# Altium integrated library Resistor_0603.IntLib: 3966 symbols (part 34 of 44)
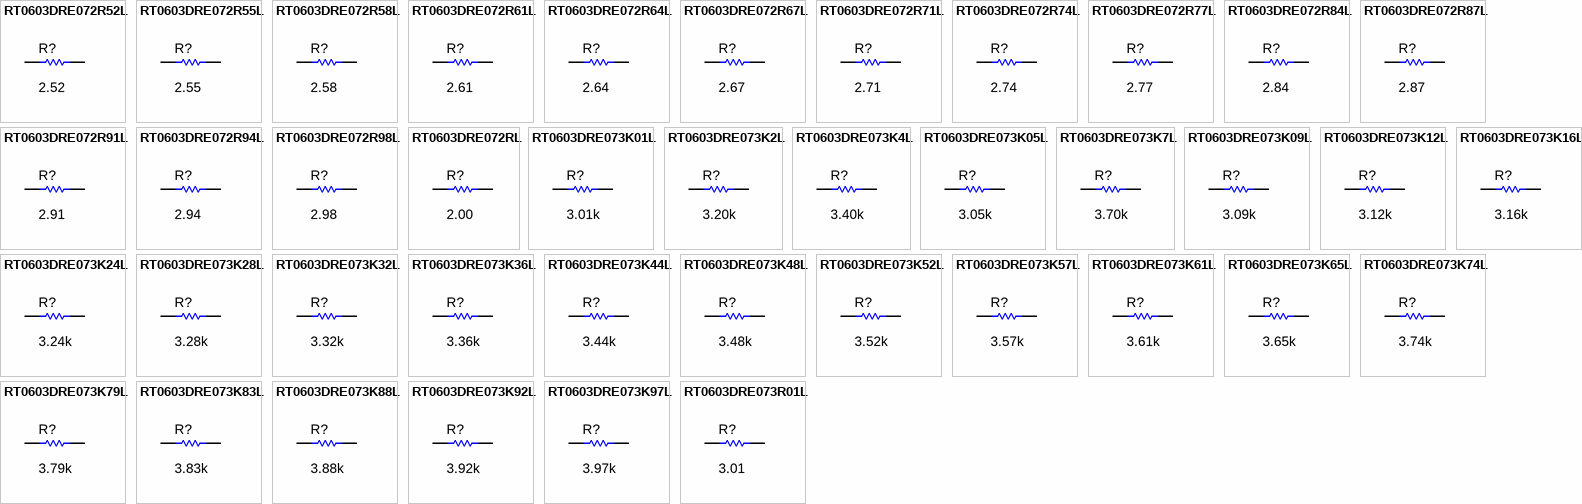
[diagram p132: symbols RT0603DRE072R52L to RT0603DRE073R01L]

## RT0603DRE073K01L
designator R?  ValueDisplayed: 3.01k  (hidden comment: RT0603DRE073K01L)
RES, 3.01 k, 0.5%, 0.1 W, 0603; Manufacturer: Yageo America; CompType: Resistor; Value: 3.01k; Res_ohm: 3010; Value_Code: 3k01; Tolerance_%: 0.5; Power_W: 0.1; Value2: 0.1W; VDC_V: 75; TempCo: 50 ppm/C; SizeArea_mm2: 1.28; SizeX_mm: 1.6; SizeY_mm: 0.8; SizeZ_mm: 1; EIA_Code: E192; U/M: EA; AEC Category: Q200
signal-integrity model Resistor
simulation model Resistor
footprint 0603
footprint 0603M
footprint 0603L
footprint 0603_HV
footprint 0603S
pins: 1, 2

## RT0603DRE073K2L
designator R?  ValueDisplayed: 3.20k  (hidden comment: RT0603DRE073K2L)
RES, 3.20 k, 0.5%, 0.1 W, 0603; Manufacturer: Yageo America; CompType: Resistor; Value: 3.20k; Res_ohm: 3200; Value_Code: 3k20; Tolerance_%: 0.5; Power_W: 0.1; Value2: 0.1W; VDC_V: 75; TempCo: 50 ppm/C; SizeArea_mm2: 1.28; SizeX_mm: 1.6; SizeY_mm: 0.8; SizeZ_mm: 1; EIA_Code: E192; U/M: EA; AEC Category: Q200
signal-integrity model Resistor
simulation model Resistor
footprint 0603
footprint 0603M
footprint 0603L
footprint 0603_HV
footprint 0603S
pins: 1, 2

## RT0603DRE073K4L
designator R?  ValueDisplayed: 3.40k  (hidden comment: RT0603DRE073K4L)
RES, 3.40 k, 0.5%, 0.1 W, 0603; Manufacturer: Yageo America; CompType: Resistor; Value: 3.40k; Res_ohm: 3400; Value_Code: 3k40; Tolerance_%: 0.5; Power_W: 0.1; Value2: 0.1W; VDC_V: 75; TempCo: 50 ppm/C; SizeArea_mm2: 1.28; SizeX_mm: 1.6; SizeY_mm: 0.8; SizeZ_mm: 1; EIA_Code: E192; U/M: EA; AEC Category: Q200
signal-integrity model Resistor
simulation model Resistor
footprint 0603
footprint 0603M
footprint 0603L
footprint 0603_HV
footprint 0603S
pins: 1, 2

## RT0603DRE073K05L
designator R?  ValueDisplayed: 3.05k  (hidden comment: RT0603DRE073K05L)
RES, 3.05 k, 0.5%, 0.1 W, 0603; Manufacturer: Yageo America; CompType: Resistor; Value: 3.05k; Res_ohm: 3050; Value_Code: 3k05; Tolerance_%: 0.5; Power_W: 0.1; Value2: 0.1W; VDC_V: 75; TempCo: 50 ppm/C; SizeArea_mm2: 1.28; SizeX_mm: 1.6; SizeY_mm: 0.8; SizeZ_mm: 1; EIA_Code: E192; U/M: EA; AEC Category: Q200
signal-integrity model Resistor
simulation model Resistor
footprint 0603
footprint 0603M
footprint 0603L
footprint 0603_HV
footprint 0603S
pins: 1, 2

## RT0603DRE073K7L
designator R?  ValueDisplayed: 3.70k  (hidden comment: RT0603DRE073K7L)
RES, 3.70 k, 0.5%, 0.1 W, 0603; Manufacturer: Yageo America; CompType: Resistor; Value: 3.70k; Res_ohm: 3700; Value_Code: 3k70; Tolerance_%: 0.5; Power_W: 0.1; Value2: 0.1W; VDC_V: 75; TempCo: 50 ppm/C; SizeArea_mm2: 1.28; SizeX_mm: 1.6; SizeY_mm: 0.8; SizeZ_mm: 1; EIA_Code: E192; U/M: EA; AEC Category: Q200
signal-integrity model Resistor
simulation model Resistor
footprint 0603
footprint 0603M
footprint 0603L
footprint 0603_HV
footprint 0603S
pins: 1, 2

## RT0603DRE073K09L
designator R?  ValueDisplayed: 3.09k  (hidden comment: RT0603DRE073K09L)
RES, 3.09 k, 0.5%, 0.1 W, 0603; Manufacturer: Yageo America; CompType: Resistor; Value: 3.09k; Res_ohm: 3090; Value_Code: 3k09; Tolerance_%: 0.5; Power_W: 0.1; Value2: 0.1W; VDC_V: 75; TempCo: 50 ppm/C; SizeArea_mm2: 1.28; SizeX_mm: 1.6; SizeY_mm: 0.8; SizeZ_mm: 1; EIA_Code: E192; U/M: EA; AEC Category: Q200
signal-integrity model Resistor
simulation model Resistor
footprint 0603
footprint 0603M
footprint 0603L
footprint 0603_HV
footprint 0603S
pins: 1, 2

## RT0603DRE073K12L
designator R?  ValueDisplayed: 3.12k  (hidden comment: RT0603DRE073K12L)
RES, 3.12 k, 0.5%, 0.1 W, 0603; Manufacturer: Yageo America; CompType: Resistor; Value: 3.12k; Res_ohm: 3120; Value_Code: 3k12; Tolerance_%: 0.5; Power_W: 0.1; Value2: 0.1W; VDC_V: 75; TempCo: 50 ppm/C; SizeArea_mm2: 1.28; SizeX_mm: 1.6; SizeY_mm: 0.8; SizeZ_mm: 1; EIA_Code: E192; U/M: EA; AEC Category: Q200
signal-integrity model Resistor
simulation model Resistor
footprint 0603
footprint 0603M
footprint 0603L
footprint 0603_HV
footprint 0603S
pins: 1, 2

## RT0603DRE073K16L
designator R?  ValueDisplayed: 3.16k  (hidden comment: RT0603DRE073K16L)
RES, 3.16 k, 0.5%, 0.1 W, 0603; Manufacturer: Yageo America; CompType: Resistor; Value: 3.16k; Res_ohm: 3160; Value_Code: 3k16; Tolerance_%: 0.5; Power_W: 0.1; Value2: 0.1W; VDC_V: 75; TempCo: 50 ppm/C; SizeArea_mm2: 1.28; SizeX_mm: 1.6; SizeY_mm: 0.8; SizeZ_mm: 1; EIA_Code: E192; U/M: EA; AEC Category: Q200
signal-integrity model Resistor
simulation model Resistor
footprint 0603
footprint 0603M
footprint 0603L
footprint 0603_HV
footprint 0603S
pins: 1, 2

## RT0603DRE073K24L
designator R?  ValueDisplayed: 3.24k  (hidden comment: RT0603DRE073K24L)
RES, 3.24 k, 0.5%, 0.1 W, 0603; Manufacturer: Yageo America; CompType: Resistor; Value: 3.24k; Res_ohm: 3240; Value_Code: 3k24; Tolerance_%: 0.5; Power_W: 0.1; Value2: 0.1W; VDC_V: 75; TempCo: 50 ppm/C; SizeArea_mm2: 1.28; SizeX_mm: 1.6; SizeY_mm: 0.8; SizeZ_mm: 1; EIA_Code: E192; U/M: EA; AEC Category: Q200
signal-integrity model Resistor
simulation model Resistor
footprint 0603
footprint 0603M
footprint 0603L
footprint 0603_HV
footprint 0603S
pins: 1, 2

## RT0603DRE073K28L
designator R?  ValueDisplayed: 3.28k  (hidden comment: RT0603DRE073K28L)
RES, 3.28 k, 0.5%, 0.1 W, 0603; Manufacturer: Yageo America; CompType: Resistor; Value: 3.28k; Res_ohm: 3280; Value_Code: 3k28; Tolerance_%: 0.5; Power_W: 0.1; Value2: 0.1W; VDC_V: 75; TempCo: 50 ppm/C; SizeArea_mm2: 1.28; SizeX_mm: 1.6; SizeY_mm: 0.8; SizeZ_mm: 1; EIA_Code: E192; U/M: EA; AEC Category: Q200
signal-integrity model Resistor
simulation model Resistor
footprint 0603
footprint 0603M
footprint 0603L
footprint 0603_HV
footprint 0603S
pins: 1, 2

## RT0603DRE073K32L
designator R?  ValueDisplayed: 3.32k  (hidden comment: RT0603DRE073K32L)
RES, 3.32 k, 0.5%, 0.1 W, 0603; Manufacturer: Yageo America; CompType: Resistor; Value: 3.32k; Res_ohm: 3320; Value_Code: 3k32; Tolerance_%: 0.5; Power_W: 0.1; Value2: 0.1W; VDC_V: 75; TempCo: 50 ppm/C; SizeArea_mm2: 1.28; SizeX_mm: 1.6; SizeY_mm: 0.8; SizeZ_mm: 1; EIA_Code: E192; U/M: EA; AEC Category: Q200
signal-integrity model Resistor
simulation model Resistor
footprint 0603
footprint 0603M
footprint 0603L
footprint 0603_HV
footprint 0603S
pins: 1, 2

## RT0603DRE073K36L
designator R?  ValueDisplayed: 3.36k  (hidden comment: RT0603DRE073K36L)
RES, 3.36 k, 0.5%, 0.1 W, 0603; Manufacturer: Yageo America; CompType: Resistor; Value: 3.36k; Res_ohm: 3360; Value_Code: 3k36; Tolerance_%: 0.5; Power_W: 0.1; Value2: 0.1W; VDC_V: 75; TempCo: 50 ppm/C; SizeArea_mm2: 1.28; SizeX_mm: 1.6; SizeY_mm: 0.8; SizeZ_mm: 1; EIA_Code: E192; U/M: EA; AEC Category: Q200
signal-integrity model Resistor
simulation model Resistor
footprint 0603
footprint 0603M
footprint 0603L
footprint 0603_HV
footprint 0603S
pins: 1, 2

## RT0603DRE073K44L
designator R?  ValueDisplayed: 3.44k  (hidden comment: RT0603DRE073K44L)
RES, 3.44 k, 0.5%, 0.1 W, 0603; Manufacturer: Yageo America; CompType: Resistor; Value: 3.44k; Res_ohm: 3440; Value_Code: 3k44; Tolerance_%: 0.5; Power_W: 0.1; Value2: 0.1W; VDC_V: 75; TempCo: 50 ppm/C; SizeArea_mm2: 1.28; SizeX_mm: 1.6; SizeY_mm: 0.8; SizeZ_mm: 1; EIA_Code: E192; U/M: EA; AEC Category: Q200
signal-integrity model Resistor
simulation model Resistor
footprint 0603
footprint 0603M
footprint 0603L
footprint 0603_HV
footprint 0603S
pins: 1, 2

## RT0603DRE073K48L
designator R?  ValueDisplayed: 3.48k  (hidden comment: RT0603DRE073K48L)
RES, 3.48 k, 0.5%, 0.1 W, 0603; Manufacturer: Yageo America; CompType: Resistor; Value: 3.48k; Res_ohm: 3480; Value_Code: 3k48; Tolerance_%: 0.5; Power_W: 0.1; Value2: 0.1W; VDC_V: 75; TempCo: 50 ppm/C; SizeArea_mm2: 1.28; SizeX_mm: 1.6; SizeY_mm: 0.8; SizeZ_mm: 1; EIA_Code: E192; U/M: EA; AEC Category: Q200
signal-integrity model Resistor
simulation model Resistor
footprint 0603
footprint 0603M
footprint 0603L
footprint 0603_HV
footprint 0603S
pins: 1, 2

## RT0603DRE073K52L
designator R?  ValueDisplayed: 3.52k  (hidden comment: RT0603DRE073K52L)
RES, 3.52 k, 0.5%, 0.1 W, 0603; Manufacturer: Yageo America; CompType: Resistor; Value: 3.52k; Res_ohm: 3520; Value_Code: 3k52; Tolerance_%: 0.5; Power_W: 0.1; Value2: 0.1W; VDC_V: 75; TempCo: 50 ppm/C; SizeArea_mm2: 1.28; SizeX_mm: 1.6; SizeY_mm: 0.8; SizeZ_mm: 1; EIA_Code: E192; U/M: EA; AEC Category: Q200
signal-integrity model Resistor
simulation model Resistor
footprint 0603
footprint 0603M
footprint 0603L
footprint 0603_HV
footprint 0603S
pins: 1, 2

## RT0603DRE073K57L
designator R?  ValueDisplayed: 3.57k  (hidden comment: RT0603DRE073K57L)
RES, 3.57 k, 0.5%, 0.1 W, 0603; Manufacturer: Yageo America; CompType: Resistor; Value: 3.57k; Res_ohm: 3570; Value_Code: 3k57; Tolerance_%: 0.5; Power_W: 0.1; Value2: 0.1W; VDC_V: 75; TempCo: 50 ppm/C; SizeArea_mm2: 1.28; SizeX_mm: 1.6; SizeY_mm: 0.8; SizeZ_mm: 1; EIA_Code: E192; U/M: EA; AEC Category: Q200
signal-integrity model Resistor
simulation model Resistor
footprint 0603
footprint 0603M
footprint 0603L
footprint 0603_HV
footprint 0603S
pins: 1, 2

## RT0603DRE073K61L
designator R?  ValueDisplayed: 3.61k  (hidden comment: RT0603DRE073K61L)
RES, 3.61 k, 0.5%, 0.1 W, 0603; Manufacturer: Yageo America; CompType: Resistor; Value: 3.61k; Res_ohm: 3610; Value_Code: 3k61; Tolerance_%: 0.5; Power_W: 0.1; Value2: 0.1W; VDC_V: 75; TempCo: 50 ppm/C; SizeArea_mm2: 1.28; SizeX_mm: 1.6; SizeY_mm: 0.8; SizeZ_mm: 1; EIA_Code: E192; U/M: EA; AEC Category: Q200
signal-integrity model Resistor
simulation model Resistor
footprint 0603
footprint 0603M
footprint 0603L
footprint 0603_HV
footprint 0603S
pins: 1, 2

## RT0603DRE073K65L
designator R?  ValueDisplayed: 3.65k  (hidden comment: RT0603DRE073K65L)
RES, 3.65 k, 0.5%, 0.1 W, 0603; Manufacturer: Yageo America; CompType: Resistor; Value: 3.65k; Res_ohm: 3650; Value_Code: 3k65; Tolerance_%: 0.5; Power_W: 0.1; Value2: 0.1W; VDC_V: 75; TempCo: 50 ppm/C; SizeArea_mm2: 1.28; SizeX_mm: 1.6; SizeY_mm: 0.8; SizeZ_mm: 1; EIA_Code: E192; U/M: EA; AEC Category: Q200
signal-integrity model Resistor
simulation model Resistor
footprint 0603
footprint 0603M
footprint 0603L
footprint 0603_HV
footprint 0603S
pins: 1, 2

## RT0603DRE073K74L
designator R?  ValueDisplayed: 3.74k  (hidden comment: RT0603DRE073K74L)
RES, 3.74 k, 0.5%, 0.1 W, 0603; Manufacturer: Yageo America; CompType: Resistor; Value: 3.74k; Res_ohm: 3740; Value_Code: 3k74; Tolerance_%: 0.5; Power_W: 0.1; Value2: 0.1W; VDC_V: 75; TempCo: 50 ppm/C; SizeArea_mm2: 1.28; SizeX_mm: 1.6; SizeY_mm: 0.8; SizeZ_mm: 1; EIA_Code: E192; U/M: EA; AEC Category: Q200
signal-integrity model Resistor
simulation model Resistor
footprint 0603
footprint 0603M
footprint 0603L
footprint 0603_HV
footprint 0603S
pins: 1, 2

## RT0603DRE073K79L
designator R?  ValueDisplayed: 3.79k  (hidden comment: RT0603DRE073K79L)
RES, 3.79 k, 0.5%, 0.1 W, 0603; Manufacturer: Yageo America; CompType: Resistor; Value: 3.79k; Res_ohm: 3790; Value_Code: 3k79; Tolerance_%: 0.5; Power_W: 0.1; Value2: 0.1W; VDC_V: 75; TempCo: 50 ppm/C; SizeArea_mm2: 1.28; SizeX_mm: 1.6; SizeY_mm: 0.8; SizeZ_mm: 1; EIA_Code: E192; U/M: EA; AEC Category: Q200
signal-integrity model Resistor
simulation model Resistor
footprint 0603
footprint 0603M
footprint 0603L
footprint 0603_HV
footprint 0603S
pins: 1, 2

## RT0603DRE073K83L
designator R?  ValueDisplayed: 3.83k  (hidden comment: RT0603DRE073K83L)
RES, 3.83 k, 0.5%, 0.1 W, 0603; Manufacturer: Yageo America; CompType: Resistor; Value: 3.83k; Res_ohm: 3830; Value_Code: 3k83; Tolerance_%: 0.5; Power_W: 0.1; Value2: 0.1W; VDC_V: 75; TempCo: 50 ppm/C; SizeArea_mm2: 1.28; SizeX_mm: 1.6; SizeY_mm: 0.8; SizeZ_mm: 1; EIA_Code: E192; U/M: EA; AEC Category: Q200
signal-integrity model Resistor
simulation model Resistor
footprint 0603
footprint 0603M
footprint 0603L
footprint 0603_HV
footprint 0603S
pins: 1, 2

## RT0603DRE073K88L
designator R?  ValueDisplayed: 3.88k  (hidden comment: RT0603DRE073K88L)
RES, 3.88 k, 0.5%, 0.1 W, 0603; Manufacturer: Yageo America; CompType: Resistor; Value: 3.88k; Res_ohm: 3880; Value_Code: 3k88; Tolerance_%: 0.5; Power_W: 0.1; Value2: 0.1W; VDC_V: 75; TempCo: 50 ppm/C; SizeArea_mm2: 1.28; SizeX_mm: 1.6; SizeY_mm: 0.8; SizeZ_mm: 1; EIA_Code: E192; U/M: EA; AEC Category: Q200
signal-integrity model Resistor
simulation model Resistor
footprint 0603
footprint 0603M
footprint 0603L
footprint 0603_HV
footprint 0603S
pins: 1, 2

## RT0603DRE073K92L
designator R?  ValueDisplayed: 3.92k  (hidden comment: RT0603DRE073K92L)
RES, 3.92 k, 0.5%, 0.1 W, 0603; Manufacturer: Yageo America; CompType: Resistor; Value: 3.92k; Res_ohm: 3920; Value_Code: 3k92; Tolerance_%: 0.5; Power_W: 0.1; Value2: 0.1W; VDC_V: 75; TempCo: 50 ppm/C; SizeArea_mm2: 1.28; SizeX_mm: 1.6; SizeY_mm: 0.8; SizeZ_mm: 1; EIA_Code: E192; U/M: EA; AEC Category: Q200
signal-integrity model Resistor
simulation model Resistor
footprint 0603
footprint 0603M
footprint 0603L
footprint 0603_HV
footprint 0603S
pins: 1, 2

## RT0603DRE073K97L
designator R?  ValueDisplayed: 3.97k  (hidden comment: RT0603DRE073K97L)
RES, 3.97 k, 0.5%, 0.1 W, 0603; Manufacturer: Yageo America; CompType: Resistor; Value: 3.97k; Res_ohm: 3970; Value_Code: 3k97; Tolerance_%: 0.5; Power_W: 0.1; Value2: 0.1W; VDC_V: 75; TempCo: 50 ppm/C; SizeArea_mm2: 1.28; SizeX_mm: 1.6; SizeY_mm: 0.8; SizeZ_mm: 1; EIA_Code: E192; U/M: EA; AEC Category: Q200
signal-integrity model Resistor
simulation model Resistor
footprint 0603
footprint 0603M
footprint 0603L
footprint 0603_HV
footprint 0603S
pins: 1, 2

## RT0603DRE073R01L
designator R?  ValueDisplayed: 3.01  (hidden comment: RT0603DRE073R01L)
RES, 3.01, 0.5%, 0.1 W, 0603; Manufacturer: Yageo America; CompType: Resistor; Value: 3.01; Value_Code: 3R01; Tolerance_%: 0.5; Power_W: 0.1; Value2: 0.1W; VDC_V: 75; TempCo: 50 ppm/C; SizeArea_mm2: 1.28; SizeX_mm: 1.6; SizeY_mm: 0.8; SizeZ_mm: 1; EIA_Code: E192; U/M: EA; AEC Category: Q200
signal-integrity model Resistor
simulation model Resistor
footprint 0603
footprint 0603M
footprint 0603L
footprint 0603_HV
footprint 0603S
pins: 1, 2

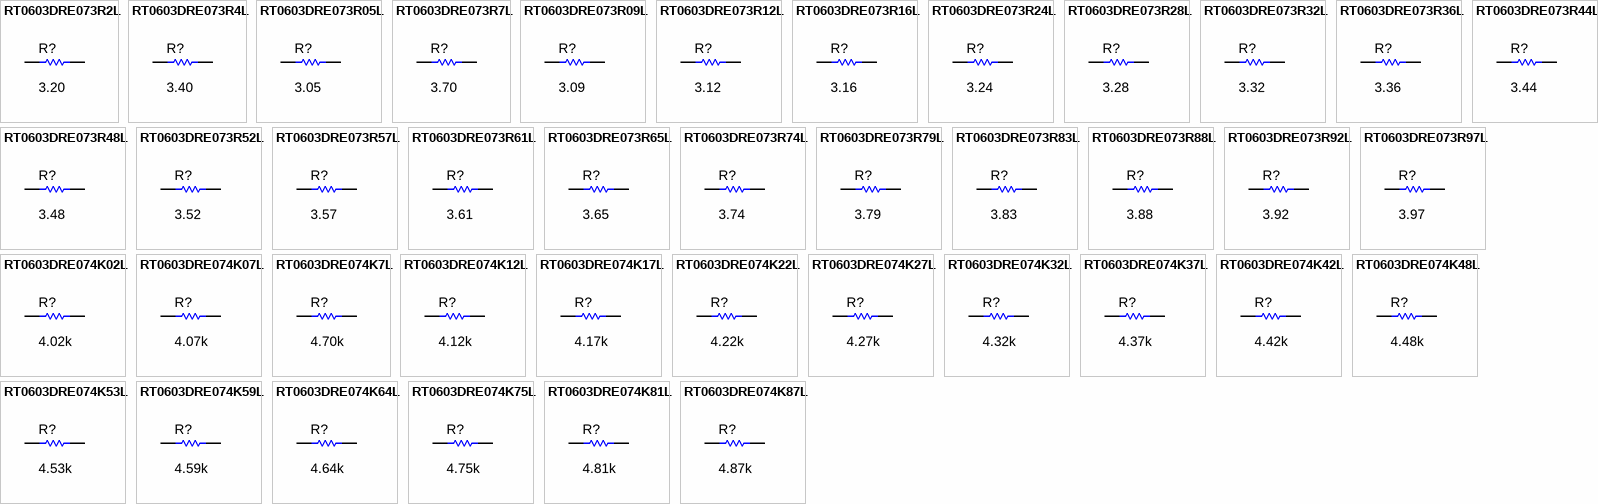
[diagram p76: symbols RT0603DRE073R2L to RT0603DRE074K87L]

## RT0603DRE073R2L
designator R?  ValueDisplayed: 3.20  (hidden comment: RT0603DRE073R2L)
RES, 3.20, 0.5%, 0.1 W, 0603; Manufacturer: Yageo America; CompType: Resistor; Value: 3.20; Res_ohm: 3.2; Value_Code: 3R20; Tolerance_%: 0.5; Power_W: 0.1; Value2: 0.1W; VDC_V: 75; TempCo: 50 ppm/C; SizeArea_mm2: 1.28; SizeX_mm: 1.6; SizeY_mm: 0.8; SizeZ_mm: 1; EIA_Code: E192; U/M: EA; AEC Category: Q200
signal-integrity model Resistor
simulation model Resistor
footprint 0603
footprint 0603M
footprint 0603L
footprint 0603_HV
footprint 0603S
pins: 1, 2

## RT0603DRE073R4L
designator R?  ValueDisplayed: 3.40  (hidden comment: RT0603DRE073R4L)
RES, 3.40, 0.5%, 0.1 W, 0603; Manufacturer: Yageo America; CompType: Resistor; Value: 3.40; Res_ohm: 3.4; Value_Code: 3R40; Tolerance_%: 0.5; Power_W: 0.1; Value2: 0.1W; VDC_V: 75; TempCo: 50 ppm/C; SizeArea_mm2: 1.28; SizeX_mm: 1.6; SizeY_mm: 0.8; SizeZ_mm: 1; EIA_Code: E192; U/M: EA; AEC Category: Q200
signal-integrity model Resistor
simulation model Resistor
footprint 0603
footprint 0603M
footprint 0603L
footprint 0603_HV
footprint 0603S
pins: 1, 2

## RT0603DRE073R05L
designator R?  ValueDisplayed: 3.05  (hidden comment: RT0603DRE073R05L)
RES, 3.05, 0.5%, 0.1 W, 0603; Manufacturer: Yageo America; CompType: Resistor; Value: 3.05; Value_Code: 3R05; Tolerance_%: 0.5; Power_W: 0.1; Value2: 0.1W; VDC_V: 75; TempCo: 50 ppm/C; SizeArea_mm2: 1.28; SizeX_mm: 1.6; SizeY_mm: 0.8; SizeZ_mm: 1; EIA_Code: E192; U/M: EA; AEC Category: Q200
signal-integrity model Resistor
simulation model Resistor
footprint 0603
footprint 0603M
footprint 0603L
footprint 0603_HV
footprint 0603S
pins: 1, 2

## RT0603DRE073R7L
designator R?  ValueDisplayed: 3.70  (hidden comment: RT0603DRE073R7L)
RES, 3.70, 0.5%, 0.1 W, 0603; Manufacturer: Yageo America; CompType: Resistor; Value: 3.70; Res_ohm: 3.7; Value_Code: 3R70; Tolerance_%: 0.5; Power_W: 0.1; Value2: 0.1W; VDC_V: 75; TempCo: 50 ppm/C; SizeArea_mm2: 1.28; SizeX_mm: 1.6; SizeY_mm: 0.8; SizeZ_mm: 1; EIA_Code: E192; U/M: EA; AEC Category: Q200
signal-integrity model Resistor
simulation model Resistor
footprint 0603
footprint 0603M
footprint 0603L
footprint 0603_HV
footprint 0603S
pins: 1, 2

## RT0603DRE073R09L
designator R?  ValueDisplayed: 3.09  (hidden comment: RT0603DRE073R09L)
RES, 3.09, 0.5%, 0.1 W, 0603; Manufacturer: Yageo America; CompType: Resistor; Value: 3.09; Value_Code: 3R09; Tolerance_%: 0.5; Power_W: 0.1; Value2: 0.1W; VDC_V: 75; TempCo: 50 ppm/C; SizeArea_mm2: 1.28; SizeX_mm: 1.6; SizeY_mm: 0.8; SizeZ_mm: 1; EIA_Code: E192; U/M: EA; AEC Category: Q200
signal-integrity model Resistor
simulation model Resistor
footprint 0603
footprint 0603M
footprint 0603L
footprint 0603_HV
footprint 0603S
pins: 1, 2

## RT0603DRE073R12L
designator R?  ValueDisplayed: 3.12  (hidden comment: RT0603DRE073R12L)
RES, 3.12, 0.5%, 0.1 W, 0603; Manufacturer: Yageo America; CompType: Resistor; Value: 3.12; Value_Code: 3R12; Tolerance_%: 0.5; Power_W: 0.1; Value2: 0.1W; VDC_V: 75; TempCo: 50 ppm/C; SizeArea_mm2: 1.28; SizeX_mm: 1.6; SizeY_mm: 0.8; SizeZ_mm: 1; EIA_Code: E192; U/M: EA; AEC Category: Q200
signal-integrity model Resistor
simulation model Resistor
footprint 0603
footprint 0603M
footprint 0603L
footprint 0603_HV
footprint 0603S
pins: 1, 2

## RT0603DRE073R16L
designator R?  ValueDisplayed: 3.16  (hidden comment: RT0603DRE073R16L)
RES, 3.16, 0.5%, 0.1 W, 0603; Manufacturer: Yageo America; CompType: Resistor; Value: 3.16; Value_Code: 3R16; Tolerance_%: 0.5; Power_W: 0.1; Value2: 0.1W; VDC_V: 75; TempCo: 50 ppm/C; SizeArea_mm2: 1.28; SizeX_mm: 1.6; SizeY_mm: 0.8; SizeZ_mm: 1; EIA_Code: E192; U/M: EA; AEC Category: Q200
signal-integrity model Resistor
simulation model Resistor
footprint 0603
footprint 0603M
footprint 0603L
footprint 0603_HV
footprint 0603S
pins: 1, 2

## RT0603DRE073R24L
designator R?  ValueDisplayed: 3.24  (hidden comment: RT0603DRE073R24L)
RES, 3.24, 0.5%, 0.1 W, 0603; Manufacturer: Yageo America; CompType: Resistor; Value: 3.24; Value_Code: 3R24; Tolerance_%: 0.5; Power_W: 0.1; Value2: 0.1W; VDC_V: 75; TempCo: 50 ppm/C; SizeArea_mm2: 1.28; SizeX_mm: 1.6; SizeY_mm: 0.8; SizeZ_mm: 1; EIA_Code: E192; U/M: EA; AEC Category: Q200
signal-integrity model Resistor
simulation model Resistor
footprint 0603
footprint 0603M
footprint 0603L
footprint 0603_HV
footprint 0603S
pins: 1, 2

## RT0603DRE073R28L
designator R?  ValueDisplayed: 3.28  (hidden comment: RT0603DRE073R28L)
RES, 3.28, 0.5%, 0.1 W, 0603; Manufacturer: Yageo America; CompType: Resistor; Value: 3.28; Value_Code: 3R28; Tolerance_%: 0.5; Power_W: 0.1; Value2: 0.1W; VDC_V: 75; TempCo: 50 ppm/C; SizeArea_mm2: 1.28; SizeX_mm: 1.6; SizeY_mm: 0.8; SizeZ_mm: 1; EIA_Code: E192; U/M: EA; AEC Category: Q200
signal-integrity model Resistor
simulation model Resistor
footprint 0603
footprint 0603M
footprint 0603L
footprint 0603_HV
footprint 0603S
pins: 1, 2

## RT0603DRE073R32L
designator R?  ValueDisplayed: 3.32  (hidden comment: RT0603DRE073R32L)
RES, 3.32, 0.5%, 0.1 W, 0603; Manufacturer: Yageo America; CompType: Resistor; Value: 3.32; Value_Code: 3R32; Tolerance_%: 0.5; Power_W: 0.1; Value2: 0.1W; VDC_V: 75; TempCo: 50 ppm/C; SizeArea_mm2: 1.28; SizeX_mm: 1.6; SizeY_mm: 0.8; SizeZ_mm: 1; EIA_Code: E192; U/M: EA; AEC Category: Q200
signal-integrity model Resistor
simulation model Resistor
footprint 0603
footprint 0603M
footprint 0603L
footprint 0603_HV
footprint 0603S
pins: 1, 2

## RT0603DRE073R36L
designator R?  ValueDisplayed: 3.36  (hidden comment: RT0603DRE073R36L)
RES, 3.36, 0.5%, 0.1 W, 0603; Manufacturer: Yageo America; CompType: Resistor; Value: 3.36; Value_Code: 3R36; Tolerance_%: 0.5; Power_W: 0.1; Value2: 0.1W; VDC_V: 75; TempCo: 50 ppm/C; SizeArea_mm2: 1.28; SizeX_mm: 1.6; SizeY_mm: 0.8; SizeZ_mm: 1; EIA_Code: E192; U/M: EA; AEC Category: Q200
signal-integrity model Resistor
simulation model Resistor
footprint 0603
footprint 0603M
footprint 0603L
footprint 0603_HV
footprint 0603S
pins: 1, 2

## RT0603DRE073R44L
designator R?  ValueDisplayed: 3.44  (hidden comment: RT0603DRE073R44L)
RES, 3.44, 0.5%, 0.1 W, 0603; Manufacturer: Yageo America; CompType: Resistor; Value: 3.44; Value_Code: 3R44; Tolerance_%: 0.5; Power_W: 0.1; Value2: 0.1W; VDC_V: 75; TempCo: 50 ppm/C; SizeArea_mm2: 1.28; SizeX_mm: 1.6; SizeY_mm: 0.8; SizeZ_mm: 1; EIA_Code: E192; U/M: EA; AEC Category: Q200
signal-integrity model Resistor
simulation model Resistor
footprint 0603
footprint 0603M
footprint 0603L
footprint 0603_HV
footprint 0603S
pins: 1, 2

## RT0603DRE073R48L
designator R?  ValueDisplayed: 3.48  (hidden comment: RT0603DRE073R48L)
RES, 3.48, 0.5%, 0.1 W, 0603; Manufacturer: Yageo America; CompType: Resistor; Value: 3.48; Value_Code: 3R48; Tolerance_%: 0.5; Power_W: 0.1; Value2: 0.1W; VDC_V: 75; TempCo: 50 ppm/C; SizeArea_mm2: 1.28; SizeX_mm: 1.6; SizeY_mm: 0.8; SizeZ_mm: 1; EIA_Code: E192; U/M: EA; AEC Category: Q200
signal-integrity model Resistor
simulation model Resistor
footprint 0603
footprint 0603M
footprint 0603L
footprint 0603_HV
footprint 0603S
pins: 1, 2

## RT0603DRE073R52L
designator R?  ValueDisplayed: 3.52  (hidden comment: RT0603DRE073R52L)
RES, 3.52, 0.5%, 0.1 W, 0603; Manufacturer: Yageo America; CompType: Resistor; Value: 3.52; Value_Code: 3R52; Tolerance_%: 0.5; Power_W: 0.1; Value2: 0.1W; VDC_V: 75; TempCo: 50 ppm/C; SizeArea_mm2: 1.28; SizeX_mm: 1.6; SizeY_mm: 0.8; SizeZ_mm: 1; EIA_Code: E192; U/M: EA; AEC Category: Q200
signal-integrity model Resistor
simulation model Resistor
footprint 0603
footprint 0603M
footprint 0603L
footprint 0603_HV
footprint 0603S
pins: 1, 2

## RT0603DRE073R57L
designator R?  ValueDisplayed: 3.57  (hidden comment: RT0603DRE073R57L)
RES, 3.57, 0.5%, 0.1 W, 0603; Manufacturer: Yageo America; CompType: Resistor; Value: 3.57; Value_Code: 3R57; Tolerance_%: 0.5; Power_W: 0.1; Value2: 0.1W; VDC_V: 75; TempCo: 50 ppm/C; SizeArea_mm2: 1.28; SizeX_mm: 1.6; SizeY_mm: 0.8; SizeZ_mm: 1; EIA_Code: E192; U/M: EA; AEC Category: Q200
signal-integrity model Resistor
simulation model Resistor
footprint 0603
footprint 0603M
footprint 0603L
footprint 0603_HV
footprint 0603S
pins: 1, 2

## RT0603DRE073R61L
designator R?  ValueDisplayed: 3.61  (hidden comment: RT0603DRE073R61L)
RES, 3.61, 0.5%, 0.1 W, 0603; Manufacturer: Yageo America; CompType: Resistor; Value: 3.61; Value_Code: 3R61; Tolerance_%: 0.5; Power_W: 0.1; Value2: 0.1W; VDC_V: 75; TempCo: 50 ppm/C; SizeArea_mm2: 1.28; SizeX_mm: 1.6; SizeY_mm: 0.8; SizeZ_mm: 1; EIA_Code: E192; U/M: EA; AEC Category: Q200
signal-integrity model Resistor
simulation model Resistor
footprint 0603
footprint 0603M
footprint 0603L
footprint 0603_HV
footprint 0603S
pins: 1, 2

## RT0603DRE073R65L
designator R?  ValueDisplayed: 3.65  (hidden comment: RT0603DRE073R65L)
RES, 3.65, 0.5%, 0.1 W, 0603; Manufacturer: Yageo America; CompType: Resistor; Value: 3.65; Value_Code: 3R65; Tolerance_%: 0.5; Power_W: 0.1; Value2: 0.1W; VDC_V: 75; TempCo: 50 ppm/C; SizeArea_mm2: 1.28; SizeX_mm: 1.6; SizeY_mm: 0.8; SizeZ_mm: 1; EIA_Code: E192; U/M: EA; AEC Category: Q200
signal-integrity model Resistor
simulation model Resistor
footprint 0603
footprint 0603M
footprint 0603L
footprint 0603_HV
footprint 0603S
pins: 1, 2

## RT0603DRE073R74L
designator R?  ValueDisplayed: 3.74  (hidden comment: RT0603DRE073R74L)
RES, 3.74, 0.5%, 0.1 W, 0603; Manufacturer: Yageo America; CompType: Resistor; Value: 3.74; Value_Code: 3R74; Tolerance_%: 0.5; Power_W: 0.1; Value2: 0.1W; VDC_V: 75; TempCo: 50 ppm/C; SizeArea_mm2: 1.28; SizeX_mm: 1.6; SizeY_mm: 0.8; SizeZ_mm: 1; EIA_Code: E192; U/M: EA; AEC Category: Q200
signal-integrity model Resistor
simulation model Resistor
footprint 0603
footprint 0603M
footprint 0603L
footprint 0603_HV
footprint 0603S
pins: 1, 2

## RT0603DRE073R79L
designator R?  ValueDisplayed: 3.79  (hidden comment: RT0603DRE073R79L)
RES, 3.79, 0.5%, 0.1 W, 0603; Manufacturer: Yageo America; CompType: Resistor; Value: 3.79; Value_Code: 3R79; Tolerance_%: 0.5; Power_W: 0.1; Value2: 0.1W; VDC_V: 75; TempCo: 50 ppm/C; SizeArea_mm2: 1.28; SizeX_mm: 1.6; SizeY_mm: 0.8; SizeZ_mm: 1; EIA_Code: E192; U/M: EA; AEC Category: Q200
signal-integrity model Resistor
simulation model Resistor
footprint 0603
footprint 0603M
footprint 0603L
footprint 0603_HV
footprint 0603S
pins: 1, 2

## RT0603DRE073R83L
designator R?  ValueDisplayed: 3.83  (hidden comment: RT0603DRE073R83L)
RES, 3.83, 0.5%, 0.1 W, 0603; Manufacturer: Yageo America; CompType: Resistor; Value: 3.83; Value_Code: 3R83; Tolerance_%: 0.5; Power_W: 0.1; Value2: 0.1W; VDC_V: 75; TempCo: 50 ppm/C; SizeArea_mm2: 1.28; SizeX_mm: 1.6; SizeY_mm: 0.8; SizeZ_mm: 1; EIA_Code: E192; U/M: EA; AEC Category: Q200
signal-integrity model Resistor
simulation model Resistor
footprint 0603
footprint 0603M
footprint 0603L
footprint 0603_HV
footprint 0603S
pins: 1, 2

## RT0603DRE073R88L
designator R?  ValueDisplayed: 3.88  (hidden comment: RT0603DRE073R88L)
RES, 3.88, 0.5%, 0.1 W, 0603; Manufacturer: Yageo America; CompType: Resistor; Value: 3.88; Value_Code: 3R88; Tolerance_%: 0.5; Power_W: 0.1; Value2: 0.1W; VDC_V: 75; TempCo: 50 ppm/C; SizeArea_mm2: 1.28; SizeX_mm: 1.6; SizeY_mm: 0.8; SizeZ_mm: 1; EIA_Code: E192; U/M: EA; AEC Category: Q200
signal-integrity model Resistor
simulation model Resistor
footprint 0603
footprint 0603M
footprint 0603L
footprint 0603_HV
footprint 0603S
pins: 1, 2

## RT0603DRE073R92L
designator R?  ValueDisplayed: 3.92  (hidden comment: RT0603DRE073R92L)
RES, 3.92, 0.5%, 0.1 W, 0603; Manufacturer: Yageo America; CompType: Resistor; Value: 3.92; Value_Code: 3R92; Tolerance_%: 0.5; Power_W: 0.1; Value2: 0.1W; VDC_V: 75; TempCo: 50 ppm/C; SizeArea_mm2: 1.28; SizeX_mm: 1.6; SizeY_mm: 0.8; SizeZ_mm: 1; EIA_Code: E192; U/M: EA; AEC Category: Q200
signal-integrity model Resistor
simulation model Resistor
footprint 0603
footprint 0603M
footprint 0603L
footprint 0603_HV
footprint 0603S
pins: 1, 2

## RT0603DRE073R97L
designator R?  ValueDisplayed: 3.97  (hidden comment: RT0603DRE073R97L)
RES, 3.97, 0.5%, 0.1 W, 0603; Manufacturer: Yageo America; CompType: Resistor; Value: 3.97; Value_Code: 3R97; Tolerance_%: 0.5; Power_W: 0.1; Value2: 0.1W; VDC_V: 75; TempCo: 50 ppm/C; SizeArea_mm2: 1.28; SizeX_mm: 1.6; SizeY_mm: 0.8; SizeZ_mm: 1; EIA_Code: E192; U/M: EA; AEC Category: Q200
signal-integrity model Resistor
simulation model Resistor
footprint 0603
footprint 0603M
footprint 0603L
footprint 0603_HV
footprint 0603S
pins: 1, 2

## RT0603DRE074K02L
designator R?  ValueDisplayed: 4.02k  (hidden comment: RT0603DRE074K02L)
RES, 4.02 k, 0.5%, 0.1 W, 0603; Manufacturer: Yageo America; CompType: Resistor; Value: 4.02k; Res_ohm: 4020; Value_Code: 4k02; Tolerance_%: 0.5; Power_W: 0.1; Value2: 0.1W; VDC_V: 75; TempCo: 50 ppm/C; SizeArea_mm2: 1.28; SizeX_mm: 1.6; SizeY_mm: 0.8; SizeZ_mm: 1; EIA_Code: E192; U/M: EA; AEC Category: Q200
signal-integrity model Resistor
simulation model Resistor
footprint 0603
footprint 0603M
footprint 0603L
footprint 0603_HV
footprint 0603S
pins: 1, 2

## RT0603DRE074K07L
designator R?  ValueDisplayed: 4.07k  (hidden comment: RT0603DRE074K07L)
RES, 4.07 k, 0.5%, 0.1 W, 0603; Manufacturer: Yageo America; CompType: Resistor; Value: 4.07k; Res_ohm: 4070; Value_Code: 4k07; Tolerance_%: 0.5; Power_W: 0.1; Value2: 0.1W; VDC_V: 75; TempCo: 50 ppm/C; SizeArea_mm2: 1.28; SizeX_mm: 1.6; SizeY_mm: 0.8; SizeZ_mm: 1; EIA_Code: E192; U/M: EA; AEC Category: Q200
signal-integrity model Resistor
simulation model Resistor
footprint 0603
footprint 0603M
footprint 0603L
footprint 0603_HV
footprint 0603S
pins: 1, 2

## RT0603DRE074K7L
designator R?  ValueDisplayed: 4.70k  (hidden comment: RT0603DRE074K7L)
RES, 4.70 k, 0.5%, 0.1 W, 0603; Manufacturer: Yageo America; CompType: Resistor; Value: 4.70k; Res_ohm: 4700; Value_Code: 4k70; Tolerance_%: 0.5; Power_W: 0.1; Value2: 0.1W; VDC_V: 75; TempCo: 50 ppm/C; SizeArea_mm2: 1.28; SizeX_mm: 1.6; SizeY_mm: 0.8; SizeZ_mm: 1; EIA_Code: E192; U/M: EA; AEC Category: Q200
signal-integrity model Resistor
simulation model Resistor
footprint 0603
footprint 0603M
footprint 0603L
footprint 0603_HV
footprint 0603S
pins: 1, 2

## RT0603DRE074K12L
designator R?  ValueDisplayed: 4.12k  (hidden comment: RT0603DRE074K12L)
RES, 4.12 k, 0.5%, 0.1 W, 0603; Manufacturer: Yageo America; CompType: Resistor; Value: 4.12k; Res_ohm: 4120; Value_Code: 4k12; Tolerance_%: 0.5; Power_W: 0.1; Value2: 0.1W; VDC_V: 75; TempCo: 50 ppm/C; SizeArea_mm2: 1.28; SizeX_mm: 1.6; SizeY_mm: 0.8; SizeZ_mm: 1; EIA_Code: E192; U/M: EA; AEC Category: Q200
signal-integrity model Resistor
simulation model Resistor
footprint 0603
footprint 0603M
footprint 0603L
footprint 0603_HV
footprint 0603S
pins: 1, 2

## RT0603DRE074K17L
designator R?  ValueDisplayed: 4.17k  (hidden comment: RT0603DRE074K17L)
RES, 4.17 k, 0.5%, 0.1 W, 0603; Manufacturer: Yageo America; CompType: Resistor; Value: 4.17k; Res_ohm: 4170; Value_Code: 4k17; Tolerance_%: 0.5; Power_W: 0.1; Value2: 0.1W; VDC_V: 75; TempCo: 50 ppm/C; SizeArea_mm2: 1.28; SizeX_mm: 1.6; SizeY_mm: 0.8; SizeZ_mm: 1; EIA_Code: E192; U/M: EA; AEC Category: Q200
signal-integrity model Resistor
simulation model Resistor
footprint 0603
footprint 0603M
footprint 0603L
footprint 0603_HV
footprint 0603S
pins: 1, 2

## RT0603DRE074K22L
designator R?  ValueDisplayed: 4.22k  (hidden comment: RT0603DRE074K22L)
RES, 4.22 k, 0.5%, 0.1 W, 0603; Manufacturer: Yageo America; CompType: Resistor; Value: 4.22k; Res_ohm: 4220; Value_Code: 4k22; Tolerance_%: 0.5; Power_W: 0.1; Value2: 0.1W; VDC_V: 75; TempCo: 50 ppm/C; SizeArea_mm2: 1.28; SizeX_mm: 1.6; SizeY_mm: 0.8; SizeZ_mm: 1; EIA_Code: E192; U/M: EA; AEC Category: Q200
signal-integrity model Resistor
simulation model Resistor
footprint 0603
footprint 0603M
footprint 0603L
footprint 0603_HV
footprint 0603S
pins: 1, 2

## RT0603DRE074K27L
designator R?  ValueDisplayed: 4.27k  (hidden comment: RT0603DRE074K27L)
RES, 4.27 k, 0.5%, 0.1 W, 0603; Manufacturer: Yageo America; CompType: Resistor; Value: 4.27k; Res_ohm: 4270; Value_Code: 4k27; Tolerance_%: 0.5; Power_W: 0.1; Value2: 0.1W; VDC_V: 75; TempCo: 50 ppm/C; SizeArea_mm2: 1.28; SizeX_mm: 1.6; SizeY_mm: 0.8; SizeZ_mm: 1; EIA_Code: E192; U/M: EA; AEC Category: Q200
signal-integrity model Resistor
simulation model Resistor
footprint 0603
footprint 0603M
footprint 0603L
footprint 0603_HV
footprint 0603S
pins: 1, 2

## RT0603DRE074K32L
designator R?  ValueDisplayed: 4.32k  (hidden comment: RT0603DRE074K32L)
RES, 4.32 k, 0.5%, 0.1 W, 0603; Manufacturer: Yageo America; CompType: Resistor; Value: 4.32k; Res_ohm: 4320; Value_Code: 4k32; Tolerance_%: 0.5; Power_W: 0.1; Value2: 0.1W; VDC_V: 75; TempCo: 50 ppm/C; SizeArea_mm2: 1.28; SizeX_mm: 1.6; SizeY_mm: 0.8; SizeZ_mm: 1; EIA_Code: E192; U/M: EA; AEC Category: Q200
signal-integrity model Resistor
simulation model Resistor
footprint 0603
footprint 0603M
footprint 0603L
footprint 0603_HV
footprint 0603S
pins: 1, 2

## RT0603DRE074K37L
designator R?  ValueDisplayed: 4.37k  (hidden comment: RT0603DRE074K37L)
RES, 4.37 k, 0.5%, 0.1 W, 0603; Manufacturer: Yageo America; CompType: Resistor; Value: 4.37k; Res_ohm: 4370; Value_Code: 4k37; Tolerance_%: 0.5; Power_W: 0.1; Value2: 0.1W; VDC_V: 75; TempCo: 50 ppm/C; SizeArea_mm2: 1.28; SizeX_mm: 1.6; SizeY_mm: 0.8; SizeZ_mm: 1; EIA_Code: E192; U/M: EA; AEC Category: Q200
signal-integrity model Resistor
simulation model Resistor
footprint 0603
footprint 0603M
footprint 0603L
footprint 0603_HV
footprint 0603S
pins: 1, 2

## RT0603DRE074K42L
designator R?  ValueDisplayed: 4.42k  (hidden comment: RT0603DRE074K42L)
RES, 4.42 k, 0.5%, 0.1 W, 0603; Manufacturer: Yageo America; CompType: Resistor; Value: 4.42k; Res_ohm: 4420; Value_Code: 4k42; Tolerance_%: 0.5; Power_W: 0.1; Value2: 0.1W; VDC_V: 75; TempCo: 50 ppm/C; SizeArea_mm2: 1.28; SizeX_mm: 1.6; SizeY_mm: 0.8; SizeZ_mm: 1; EIA_Code: E192; U/M: EA; AEC Category: Q200
signal-integrity model Resistor
simulation model Resistor
footprint 0603
footprint 0603M
footprint 0603L
footprint 0603_HV
footprint 0603S
pins: 1, 2

## RT0603DRE074K48L
designator R?  ValueDisplayed: 4.48k  (hidden comment: RT0603DRE074K48L)
RES, 4.48 k, 0.5%, 0.1 W, 0603; Manufacturer: Yageo America; CompType: Resistor; Value: 4.48k; Res_ohm: 4480; Value_Code: 4k48; Tolerance_%: 0.5; Power_W: 0.1; Value2: 0.1W; VDC_V: 75; TempCo: 50 ppm/C; SizeArea_mm2: 1.28; SizeX_mm: 1.6; SizeY_mm: 0.8; SizeZ_mm: 1; EIA_Code: E192; U/M: EA; AEC Category: Q200
signal-integrity model Resistor
simulation model Resistor
footprint 0603
footprint 0603M
footprint 0603L
footprint 0603_HV
footprint 0603S
pins: 1, 2

## RT0603DRE074K53L
designator R?  ValueDisplayed: 4.53k  (hidden comment: RT0603DRE074K53L)
RES, 4.53 k, 0.5%, 0.1 W, 0603; Manufacturer: Yageo America; CompType: Resistor; Value: 4.53k; Res_ohm: 4530; Value_Code: 4k53; Tolerance_%: 0.5; Power_W: 0.1; Value2: 0.1W; VDC_V: 75; TempCo: 50 ppm/C; SizeArea_mm2: 1.28; SizeX_mm: 1.6; SizeY_mm: 0.8; SizeZ_mm: 1; EIA_Code: E192; U/M: EA; AEC Category: Q200
signal-integrity model Resistor
simulation model Resistor
footprint 0603
footprint 0603M
footprint 0603L
footprint 0603_HV
footprint 0603S
pins: 1, 2

## RT0603DRE074K59L
designator R?  ValueDisplayed: 4.59k  (hidden comment: RT0603DRE074K59L)
RES, 4.59 k, 0.5%, 0.1 W, 0603; Manufacturer: Yageo America; CompType: Resistor; Value: 4.59k; Res_ohm: 4590; Value_Code: 4k59; Tolerance_%: 0.5; Power_W: 0.1; Value2: 0.1W; VDC_V: 75; TempCo: 50 ppm/C; SizeArea_mm2: 1.28; SizeX_mm: 1.6; SizeY_mm: 0.8; SizeZ_mm: 1; EIA_Code: E192; U/M: EA; AEC Category: Q200
signal-integrity model Resistor
simulation model Resistor
footprint 0603
footprint 0603M
footprint 0603L
footprint 0603_HV
footprint 0603S
pins: 1, 2

## RT0603DRE074K64L
designator R?  ValueDisplayed: 4.64k  (hidden comment: RT0603DRE074K64L)
RES, 4.64 k, 0.5%, 0.1 W, 0603; Manufacturer: Yageo America; CompType: Resistor; Value: 4.64k; Res_ohm: 4640; Value_Code: 4k64; Tolerance_%: 0.5; Power_W: 0.1; Value2: 0.1W; VDC_V: 75; TempCo: 50 ppm/C; SizeArea_mm2: 1.28; SizeX_mm: 1.6; SizeY_mm: 0.8; SizeZ_mm: 1; EIA_Code: E192; U/M: EA; AEC Category: Q200
signal-integrity model Resistor
simulation model Resistor
footprint 0603
footprint 0603M
footprint 0603L
footprint 0603_HV
footprint 0603S
pins: 1, 2

## RT0603DRE074K75L
designator R?  ValueDisplayed: 4.75k  (hidden comment: RT0603DRE074K75L)
RES, 4.75 k, 0.5%, 0.1 W, 0603; Manufacturer: Yageo America; CompType: Resistor; Value: 4.75k; Res_ohm: 4750; Value_Code: 4k75; Tolerance_%: 0.5; Power_W: 0.1; Value2: 0.1W; VDC_V: 75; TempCo: 50 ppm/C; SizeArea_mm2: 1.28; SizeX_mm: 1.6; SizeY_mm: 0.8; SizeZ_mm: 1; EIA_Code: E192; U/M: EA; AEC Category: Q200
signal-integrity model Resistor
simulation model Resistor
footprint 0603
footprint 0603M
footprint 0603L
footprint 0603_HV
footprint 0603S
pins: 1, 2

## RT0603DRE074K81L
designator R?  ValueDisplayed: 4.81k  (hidden comment: RT0603DRE074K81L)
RES, 4.81 k, 0.5%, 0.1 W, 0603; Manufacturer: Yageo America; CompType: Resistor; Value: 4.81k; Res_ohm: 4810; Value_Code: 4k81; Tolerance_%: 0.5; Power_W: 0.1; Value2: 0.1W; VDC_V: 75; TempCo: 50 ppm/C; SizeArea_mm2: 1.28; SizeX_mm: 1.6; SizeY_mm: 0.8; SizeZ_mm: 1; EIA_Code: E192; U/M: EA; AEC Category: Q200
signal-integrity model Resistor
simulation model Resistor
footprint 0603
footprint 0603M
footprint 0603L
footprint 0603_HV
footprint 0603S
pins: 1, 2

## RT0603DRE074K87L
designator R?  ValueDisplayed: 4.87k  (hidden comment: RT0603DRE074K87L)
RES, 4.87 k, 0.5%, 0.1 W, 0603; Manufacturer: Yageo America; CompType: Resistor; Value: 4.87k; Res_ohm: 4870; Value_Code: 4k87; Tolerance_%: 0.5; Power_W: 0.1; Value2: 0.1W; VDC_V: 75; TempCo: 50 ppm/C; SizeArea_mm2: 1.28; SizeX_mm: 1.6; SizeY_mm: 0.8; SizeZ_mm: 1; EIA_Code: E192; U/M: EA; AEC Category: Q200
signal-integrity model Resistor
simulation model Resistor
footprint 0603
footprint 0603M
footprint 0603L
footprint 0603_HV
footprint 0603S
pins: 1, 2

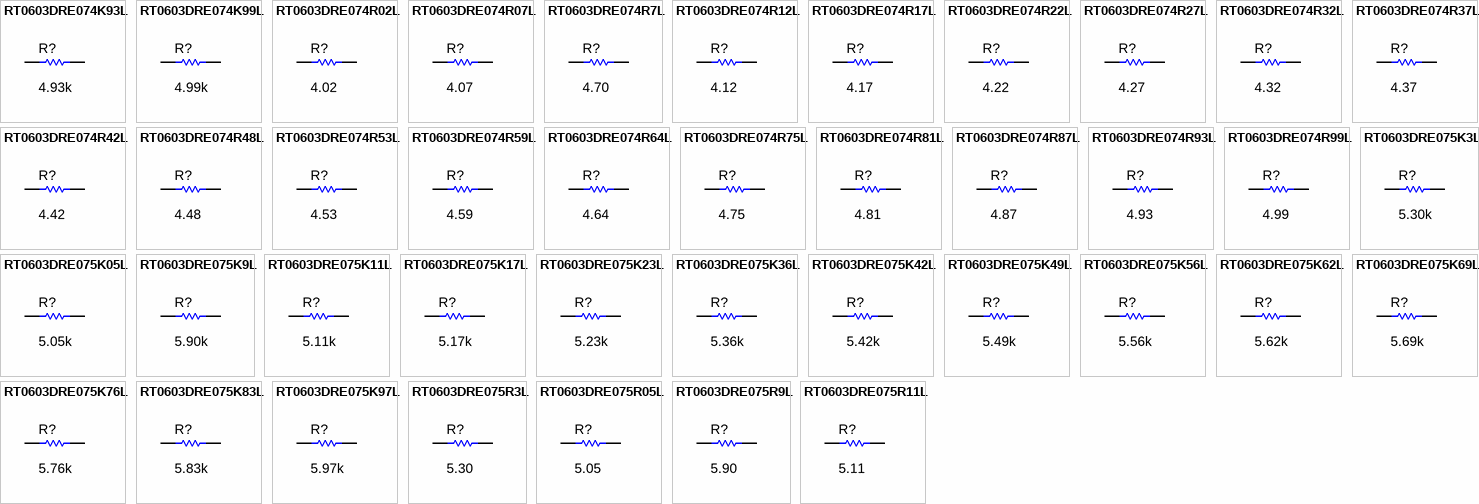
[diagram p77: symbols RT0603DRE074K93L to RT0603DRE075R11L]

## RT0603DRE074K93L
designator R?  ValueDisplayed: 4.93k  (hidden comment: RT0603DRE074K93L)
RES, 4.93 k, 0.5%, 0.1 W, 0603; Manufacturer: Yageo America; CompType: Resistor; Value: 4.93k; Res_ohm: 4930; Value_Code: 4k93; Tolerance_%: 0.5; Power_W: 0.1; Value2: 0.1W; VDC_V: 75; TempCo: 50 ppm/C; SizeArea_mm2: 1.28; SizeX_mm: 1.6; SizeY_mm: 0.8; SizeZ_mm: 1; EIA_Code: E192; U/M: EA; AEC Category: Q200
signal-integrity model Resistor
simulation model Resistor
footprint 0603
footprint 0603M
footprint 0603L
footprint 0603_HV
footprint 0603S
pins: 1, 2

## RT0603DRE074K99L
designator R?  ValueDisplayed: 4.99k  (hidden comment: RT0603DRE074K99L)
RES, 4.99 k, 0.5%, 0.1 W, 0603; Manufacturer: Yageo America; CompType: Resistor; Value: 4.99k; Res_ohm: 4990; Value_Code: 4k99; Tolerance_%: 0.5; Power_W: 0.1; Value2: 0.1W; VDC_V: 75; TempCo: 50 ppm/C; SizeArea_mm2: 1.28; SizeX_mm: 1.6; SizeY_mm: 0.8; SizeZ_mm: 1; EIA_Code: E192; U/M: EA; AEC Category: Q200; Green_Lifecycle: Active; Green_REACh: Passed
signal-integrity model Resistor
simulation model Resistor
footprint 0603
footprint 0603M
footprint 0603L
footprint 0603_HV
footprint 0603S
pins: 1, 2

## RT0603DRE074R02L
designator R?  ValueDisplayed: 4.02  (hidden comment: RT0603DRE074R02L)
RES, 4.02, 0.5%, 0.1 W, 0603; Manufacturer: Yageo America; CompType: Resistor; Value: 4.02; Value_Code: 4R02; Tolerance_%: 0.5; Power_W: 0.1; Value2: 0.1W; VDC_V: 75; TempCo: 50 ppm/C; SizeArea_mm2: 1.28; SizeX_mm: 1.6; SizeY_mm: 0.8; SizeZ_mm: 1; EIA_Code: E192; U/M: EA; AEC Category: Q200
signal-integrity model Resistor
simulation model Resistor
footprint 0603
footprint 0603M
footprint 0603L
footprint 0603_HV
footprint 0603S
pins: 1, 2

## RT0603DRE074R07L
designator R?  ValueDisplayed: 4.07  (hidden comment: RT0603DRE074R07L)
RES, 4.07, 0.5%, 0.1 W, 0603; Manufacturer: Yageo America; CompType: Resistor; Value: 4.07; Value_Code: 4R07; Tolerance_%: 0.5; Power_W: 0.1; Value2: 0.1W; VDC_V: 75; TempCo: 50 ppm/C; SizeArea_mm2: 1.28; SizeX_mm: 1.6; SizeY_mm: 0.8; SizeZ_mm: 1; EIA_Code: E192; U/M: EA; AEC Category: Q200
signal-integrity model Resistor
simulation model Resistor
footprint 0603
footprint 0603M
footprint 0603L
footprint 0603_HV
footprint 0603S
pins: 1, 2

## RT0603DRE074R7L
designator R?  ValueDisplayed: 4.70  (hidden comment: RT0603DRE074R7L)
RES, 4.70, 0.5%, 0.1 W, 0603; Manufacturer: Yageo America; CompType: Resistor; Value: 4.70; Res_ohm: 4.7; Value_Code: 4R70; Tolerance_%: 0.5; Power_W: 0.1; Value2: 0.1W; VDC_V: 75; TempCo: 50 ppm/C; SizeArea_mm2: 1.28; SizeX_mm: 1.6; SizeY_mm: 0.8; SizeZ_mm: 1; EIA_Code: E192; U/M: EA; AEC Category: Q200; Green_Lifecycle: Active; Green_REACh: Passed
signal-integrity model Resistor
simulation model Resistor
footprint 0603
footprint 0603M
footprint 0603L
footprint 0603_HV
footprint 0603S
pins: 1, 2

## RT0603DRE074R12L
designator R?  ValueDisplayed: 4.12  (hidden comment: RT0603DRE074R12L)
RES, 4.12, 0.5%, 0.1 W, 0603; Manufacturer: Yageo America; CompType: Resistor; Value: 4.12; Value_Code: 4R12; Tolerance_%: 0.5; Power_W: 0.1; Value2: 0.1W; VDC_V: 75; TempCo: 50 ppm/C; SizeArea_mm2: 1.28; SizeX_mm: 1.6; SizeY_mm: 0.8; SizeZ_mm: 1; EIA_Code: E192; U/M: EA; AEC Category: Q200
signal-integrity model Resistor
simulation model Resistor
footprint 0603
footprint 0603M
footprint 0603L
footprint 0603_HV
footprint 0603S
pins: 1, 2

## RT0603DRE074R17L
designator R?  ValueDisplayed: 4.17  (hidden comment: RT0603DRE074R17L)
RES, 4.17, 0.5%, 0.1 W, 0603; Manufacturer: Yageo America; CompType: Resistor; Value: 4.17; Value_Code: 4R17; Tolerance_%: 0.5; Power_W: 0.1; Value2: 0.1W; VDC_V: 75; TempCo: 50 ppm/C; SizeArea_mm2: 1.28; SizeX_mm: 1.6; SizeY_mm: 0.8; SizeZ_mm: 1; EIA_Code: E192; U/M: EA; AEC Category: Q200
signal-integrity model Resistor
simulation model Resistor
footprint 0603
footprint 0603M
footprint 0603L
footprint 0603_HV
footprint 0603S
pins: 1, 2

## RT0603DRE074R22L
designator R?  ValueDisplayed: 4.22  (hidden comment: RT0603DRE074R22L)
RES, 4.22, 0.5%, 0.1 W, 0603; Manufacturer: Yageo America; CompType: Resistor; Value: 4.22; Value_Code: 4R22; Tolerance_%: 0.5; Power_W: 0.1; Value2: 0.1W; VDC_V: 75; TempCo: 50 ppm/C; SizeArea_mm2: 1.28; SizeX_mm: 1.6; SizeY_mm: 0.8; SizeZ_mm: 1; EIA_Code: E192; U/M: EA; AEC Category: Q200
signal-integrity model Resistor
simulation model Resistor
footprint 0603
footprint 0603M
footprint 0603L
footprint 0603_HV
footprint 0603S
pins: 1, 2

## RT0603DRE074R27L
designator R?  ValueDisplayed: 4.27  (hidden comment: RT0603DRE074R27L)
RES, 4.27, 0.5%, 0.1 W, 0603; Manufacturer: Yageo America; CompType: Resistor; Value: 4.27; Value_Code: 4R27; Tolerance_%: 0.5; Power_W: 0.1; Value2: 0.1W; VDC_V: 75; TempCo: 50 ppm/C; SizeArea_mm2: 1.28; SizeX_mm: 1.6; SizeY_mm: 0.8; SizeZ_mm: 1; EIA_Code: E192; U/M: EA; AEC Category: Q200
signal-integrity model Resistor
simulation model Resistor
footprint 0603
footprint 0603M
footprint 0603L
footprint 0603_HV
footprint 0603S
pins: 1, 2

## RT0603DRE074R32L
designator R?  ValueDisplayed: 4.32  (hidden comment: RT0603DRE074R32L)
RES, 4.32, 0.5%, 0.1 W, 0603; Manufacturer: Yageo America; CompType: Resistor; Value: 4.32; Value_Code: 4R32; Tolerance_%: 0.5; Power_W: 0.1; Value2: 0.1W; VDC_V: 75; TempCo: 50 ppm/C; SizeArea_mm2: 1.28; SizeX_mm: 1.6; SizeY_mm: 0.8; SizeZ_mm: 1; EIA_Code: E192; U/M: EA; AEC Category: Q200
signal-integrity model Resistor
simulation model Resistor
footprint 0603
footprint 0603M
footprint 0603L
footprint 0603_HV
footprint 0603S
pins: 1, 2

## RT0603DRE074R37L
designator R?  ValueDisplayed: 4.37  (hidden comment: RT0603DRE074R37L)
RES, 4.37, 0.5%, 0.1 W, 0603; Manufacturer: Yageo America; CompType: Resistor; Value: 4.37; Value_Code: 4R37; Tolerance_%: 0.5; Power_W: 0.1; Value2: 0.1W; VDC_V: 75; TempCo: 50 ppm/C; SizeArea_mm2: 1.28; SizeX_mm: 1.6; SizeY_mm: 0.8; SizeZ_mm: 1; EIA_Code: E192; U/M: EA; AEC Category: Q200
signal-integrity model Resistor
simulation model Resistor
footprint 0603
footprint 0603M
footprint 0603L
footprint 0603_HV
footprint 0603S
pins: 1, 2

## RT0603DRE074R42L
designator R?  ValueDisplayed: 4.42  (hidden comment: RT0603DRE074R42L)
RES, 4.42, 0.5%, 0.1 W, 0603; Manufacturer: Yageo America; CompType: Resistor; Value: 4.42; Value_Code: 4R42; Tolerance_%: 0.5; Power_W: 0.1; Value2: 0.1W; VDC_V: 75; TempCo: 50 ppm/C; SizeArea_mm2: 1.28; SizeX_mm: 1.6; SizeY_mm: 0.8; SizeZ_mm: 1; EIA_Code: E192; U/M: EA; AEC Category: Q200
signal-integrity model Resistor
simulation model Resistor
footprint 0603
footprint 0603M
footprint 0603L
footprint 0603_HV
footprint 0603S
pins: 1, 2

## RT0603DRE074R48L
designator R?  ValueDisplayed: 4.48  (hidden comment: RT0603DRE074R48L)
RES, 4.48, 0.5%, 0.1 W, 0603; Manufacturer: Yageo America; CompType: Resistor; Value: 4.48; Value_Code: 4R48; Tolerance_%: 0.5; Power_W: 0.1; Value2: 0.1W; VDC_V: 75; TempCo: 50 ppm/C; SizeArea_mm2: 1.28; SizeX_mm: 1.6; SizeY_mm: 0.8; SizeZ_mm: 1; EIA_Code: E192; U/M: EA; AEC Category: Q200
signal-integrity model Resistor
simulation model Resistor
footprint 0603
footprint 0603M
footprint 0603L
footprint 0603_HV
footprint 0603S
pins: 1, 2

## RT0603DRE074R53L
designator R?  ValueDisplayed: 4.53  (hidden comment: RT0603DRE074R53L)
RES, 4.53, 0.5%, 0.1 W, 0603; Manufacturer: Yageo America; CompType: Resistor; Value: 4.53; Value_Code: 4R53; Tolerance_%: 0.5; Power_W: 0.1; Value2: 0.1W; VDC_V: 75; TempCo: 50 ppm/C; SizeArea_mm2: 1.28; SizeX_mm: 1.6; SizeY_mm: 0.8; SizeZ_mm: 1; EIA_Code: E192; U/M: EA; AEC Category: Q200
signal-integrity model Resistor
simulation model Resistor
footprint 0603
footprint 0603M
footprint 0603L
footprint 0603_HV
footprint 0603S
pins: 1, 2

## RT0603DRE074R59L
designator R?  ValueDisplayed: 4.59  (hidden comment: RT0603DRE074R59L)
RES, 4.59, 0.5%, 0.1 W, 0603; Manufacturer: Yageo America; CompType: Resistor; Value: 4.59; Value_Code: 4R59; Tolerance_%: 0.5; Power_W: 0.1; Value2: 0.1W; VDC_V: 75; TempCo: 50 ppm/C; SizeArea_mm2: 1.28; SizeX_mm: 1.6; SizeY_mm: 0.8; SizeZ_mm: 1; EIA_Code: E192; U/M: EA; AEC Category: Q200
signal-integrity model Resistor
simulation model Resistor
footprint 0603
footprint 0603M
footprint 0603L
footprint 0603_HV
footprint 0603S
pins: 1, 2

## RT0603DRE074R64L
designator R?  ValueDisplayed: 4.64  (hidden comment: RT0603DRE074R64L)
RES, 4.64, 0.5%, 0.1 W, 0603; Manufacturer: Yageo America; CompType: Resistor; Value: 4.64; Value_Code: 4R64; Tolerance_%: 0.5; Power_W: 0.1; Value2: 0.1W; VDC_V: 75; TempCo: 50 ppm/C; SizeArea_mm2: 1.28; SizeX_mm: 1.6; SizeY_mm: 0.8; SizeZ_mm: 1; EIA_Code: E192; U/M: EA; AEC Category: Q200
signal-integrity model Resistor
simulation model Resistor
footprint 0603
footprint 0603M
footprint 0603L
footprint 0603_HV
footprint 0603S
pins: 1, 2

## RT0603DRE074R75L
designator R?  ValueDisplayed: 4.75  (hidden comment: RT0603DRE074R75L)
RES, 4.75, 0.5%, 0.1 W, 0603; Manufacturer: Yageo America; CompType: Resistor; Value: 4.75; Value_Code: 4R75; Tolerance_%: 0.5; Power_W: 0.1; Value2: 0.1W; VDC_V: 75; TempCo: 50 ppm/C; SizeArea_mm2: 1.28; SizeX_mm: 1.6; SizeY_mm: 0.8; SizeZ_mm: 1; EIA_Code: E192; U/M: EA; AEC Category: Q200
signal-integrity model Resistor
simulation model Resistor
footprint 0603
footprint 0603M
footprint 0603L
footprint 0603_HV
footprint 0603S
pins: 1, 2

## RT0603DRE074R81L
designator R?  ValueDisplayed: 4.81  (hidden comment: RT0603DRE074R81L)
RES, 4.81, 0.5%, 0.1 W, 0603; Manufacturer: Yageo America; CompType: Resistor; Value: 4.81; Value_Code: 4R81; Tolerance_%: 0.5; Power_W: 0.1; Value2: 0.1W; VDC_V: 75; TempCo: 50 ppm/C; SizeArea_mm2: 1.28; SizeX_mm: 1.6; SizeY_mm: 0.8; SizeZ_mm: 1; EIA_Code: E192; U/M: EA; AEC Category: Q200
signal-integrity model Resistor
simulation model Resistor
footprint 0603
footprint 0603M
footprint 0603L
footprint 0603_HV
footprint 0603S
pins: 1, 2

## RT0603DRE074R87L
designator R?  ValueDisplayed: 4.87  (hidden comment: RT0603DRE074R87L)
RES, 4.87, 0.5%, 0.1 W, 0603; Manufacturer: Yageo America; CompType: Resistor; Value: 4.87; Value_Code: 4R87; Tolerance_%: 0.5; Power_W: 0.1; Value2: 0.1W; VDC_V: 75; TempCo: 50 ppm/C; SizeArea_mm2: 1.28; SizeX_mm: 1.6; SizeY_mm: 0.8; SizeZ_mm: 1; EIA_Code: E192; U/M: EA; AEC Category: Q200
signal-integrity model Resistor
simulation model Resistor
footprint 0603
footprint 0603M
footprint 0603L
footprint 0603_HV
footprint 0603S
pins: 1, 2

## RT0603DRE074R93L
designator R?  ValueDisplayed: 4.93  (hidden comment: RT0603DRE074R93L)
RES, 4.93, 0.5%, 0.1 W, 0603; Manufacturer: Yageo America; CompType: Resistor; Value: 4.93; Value_Code: 4R93; Tolerance_%: 0.5; Power_W: 0.1; Value2: 0.1W; VDC_V: 75; TempCo: 50 ppm/C; SizeArea_mm2: 1.28; SizeX_mm: 1.6; SizeY_mm: 0.8; SizeZ_mm: 1; EIA_Code: E192; U/M: EA; AEC Category: Q200
signal-integrity model Resistor
simulation model Resistor
footprint 0603
footprint 0603M
footprint 0603L
footprint 0603_HV
footprint 0603S
pins: 1, 2

## RT0603DRE074R99L
designator R?  ValueDisplayed: 4.99  (hidden comment: RT0603DRE074R99L)
RES, 4.99, 0.5%, 0.1 W, 0603; Manufacturer: Yageo America; CompType: Resistor; Value: 4.99; Value_Code: 4R99; Tolerance_%: 0.5; Power_W: 0.1; Value2: 0.1W; VDC_V: 75; TempCo: 50 ppm/C; SizeArea_mm2: 1.28; SizeX_mm: 1.6; SizeY_mm: 0.8; SizeZ_mm: 1; EIA_Code: E192; U/M: EA; AEC Category: Q200
signal-integrity model Resistor
simulation model Resistor
footprint 0603
footprint 0603M
footprint 0603L
footprint 0603_HV
footprint 0603S
pins: 1, 2

## RT0603DRE075K3L
designator R?  ValueDisplayed: 5.30k  (hidden comment: RT0603DRE075K3L)
RES, 5.30 k, 0.5%, 0.1 W, 0603; Manufacturer: Yageo America; CompType: Resistor; Value: 5.30k; Res_ohm: 5300; Value_Code: 5k30; Tolerance_%: 0.5; Power_W: 0.1; Value2: 0.1W; VDC_V: 75; TempCo: 50 ppm/C; SizeArea_mm2: 1.28; SizeX_mm: 1.6; SizeY_mm: 0.8; SizeZ_mm: 1; EIA_Code: E192; U/M: EA; AEC Category: Q200
signal-integrity model Resistor
simulation model Resistor
footprint 0603
footprint 0603M
footprint 0603L
footprint 0603_HV
footprint 0603S
pins: 1, 2

## RT0603DRE075K05L
designator R?  ValueDisplayed: 5.05k  (hidden comment: RT0603DRE075K05L)
RES, 5.05 k, 0.5%, 0.1 W, 0603; Manufacturer: Yageo America; CompType: Resistor; Value: 5.05k; Res_ohm: 5050; Value_Code: 5k05; Tolerance_%: 0.5; Power_W: 0.1; Value2: 0.1W; VDC_V: 75; TempCo: 50 ppm/C; SizeArea_mm2: 1.28; SizeX_mm: 1.6; SizeY_mm: 0.8; SizeZ_mm: 1; EIA_Code: E192; U/M: EA; AEC Category: Q200
signal-integrity model Resistor
simulation model Resistor
footprint 0603
footprint 0603M
footprint 0603L
footprint 0603_HV
footprint 0603S
pins: 1, 2

## RT0603DRE075K9L
designator R?  ValueDisplayed: 5.90k  (hidden comment: RT0603DRE075K9L)
RES, 5.90 k, 0.5%, 0.1 W, 0603; Manufacturer: Yageo America; CompType: Resistor; Value: 5.90k; Res_ohm: 5900; Value_Code: 5k90; Tolerance_%: 0.5; Power_W: 0.1; Value2: 0.1W; VDC_V: 75; TempCo: 50 ppm/C; SizeArea_mm2: 1.28; SizeX_mm: 1.6; SizeY_mm: 0.8; SizeZ_mm: 1; EIA_Code: E192; U/M: EA; AEC Category: Q200
signal-integrity model Resistor
simulation model Resistor
footprint 0603
footprint 0603M
footprint 0603L
footprint 0603_HV
footprint 0603S
pins: 1, 2

## RT0603DRE075K11L
designator R?  ValueDisplayed: 5.11k  (hidden comment: RT0603DRE075K11L)
RES, 5.11 k, 0.5%, 0.1 W, 0603; Manufacturer: Yageo America; CompType: Resistor; Value: 5.11k; Res_ohm: 5110; Value_Code: 5k11; Tolerance_%: 0.5; Power_W: 0.1; Value2: 0.1W; VDC_V: 75; TempCo: 50 ppm/C; SizeArea_mm2: 1.28; SizeX_mm: 1.6; SizeY_mm: 0.8; SizeZ_mm: 1; EIA_Code: E192; U/M: EA; AEC Category: Q200
signal-integrity model Resistor
simulation model Resistor
footprint 0603
footprint 0603M
footprint 0603L
footprint 0603_HV
footprint 0603S
pins: 1, 2

## RT0603DRE075K17L
designator R?  ValueDisplayed: 5.17k  (hidden comment: RT0603DRE075K17L)
RES, 5.17 k, 0.5%, 0.1 W, 0603; Manufacturer: Yageo America; CompType: Resistor; Value: 5.17k; Res_ohm: 5170; Value_Code: 5k17; Tolerance_%: 0.5; Power_W: 0.1; Value2: 0.1W; VDC_V: 75; TempCo: 50 ppm/C; SizeArea_mm2: 1.28; SizeX_mm: 1.6; SizeY_mm: 0.8; SizeZ_mm: 1; EIA_Code: E192; U/M: EA; AEC Category: Q200
signal-integrity model Resistor
simulation model Resistor
footprint 0603
footprint 0603M
footprint 0603L
footprint 0603_HV
footprint 0603S
pins: 1, 2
